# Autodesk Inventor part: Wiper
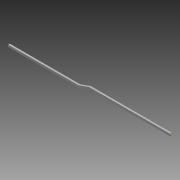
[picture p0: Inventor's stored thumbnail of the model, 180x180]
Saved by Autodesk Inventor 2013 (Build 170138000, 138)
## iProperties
Created: 2006-03
Part Number: Wiper
Document SubType Name: Modeling
Designer: debonom
Material: Stainless Steel, 440C
Mass: 28.0148 g
Surface Area: 42.4106 cm^2
Volume: 3.61481 cm^3
Density: 7.75 g/cm^3
Author: debonom
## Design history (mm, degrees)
sketch "Sketch1"
  geometry: L1 (-1.5, 2)-(1.5, 2); L2 (1.5, 2)-(1.5, -2); L3 (1.5, -2)-(-1.5, -2); L4 (-1.5, -2)-(-1.5, 2); L5 (-1.5, 2)-(1.5, -2); 2 further points
  constraints: 10 end point, 2 parallel, 1 coincident, 1 horizontal, 1 midpoint, 1 perpendicular
  dimensions: "d0" = 3 distance of L1.start L1.end; "d1" = 4 distance of L3.end L1.start
sketch "Sketch2"
  geometry: L1 (0, 0)-(150, 0); L2 (150, 0)-(169.232, -7); L3 (169.232, -7)-(300, -7)
  constraints: 6 end point, 1 horizontal, 1 parallel
  dimensions: "d2" = 150 distance of L1.start L1.end; "d3" = 160 deg angle of L2 L1; "d4" = 300 horizontal distance of L3.end L1.start; "d5" = 7 distance between parallel lines of L3 L1
sweep "Sweep1" sketch "Sketch1", "Sketch2" dims "d6" = 0
fillet "Fillet1" dims "d7" = 5
workaxis "Work Axis1"
workaxis "Work Axis2"
body "Solid1"
